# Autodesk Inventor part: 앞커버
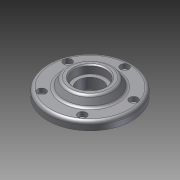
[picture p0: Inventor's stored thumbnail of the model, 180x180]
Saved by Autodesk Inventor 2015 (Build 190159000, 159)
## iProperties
Company: 한국ATC센터
Created: 2014-03
Part Number: 앞커버
Document SubType Name: Modeling
Designer: KYOUNG IL JANG
Density: 1 g/cm^3
Material: 일반
Appearance: Default
Author: KYOUNG IL JANG
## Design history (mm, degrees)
sketch "스케치1"
  geometry: C1 r 26 at (0, 0); C2 r 40 at (0, 0); 1 further point
  constraints: 2 centre point, 2 coincident
  dimensions: "d0" = 52 diameter of C1; "d1" = 80 diameter of C2
extrude "돌출1" new body sketch "스케치1" distance "d2" = 8; taper "d3" = 0 deg
extrude "돌출2" join sketch "스케치1" distance "d4" = 5; taper "d5" = 0 deg
sketch "스케치2"
  geometry: C1 r 25 at (0, 0); 1 further point
  constraints: 1 centre point, 1 coincident
  dimensions: "d6" = 50 diameter of C1
extrude "돌출3" join sketch "스케치2" distance "d7" = 8; taper "d8" = -30 deg
sketch "스케치3"
  geometry: C1 r 1.729 at (0, 33) reference; 1 further point
hole "구멍1" sketch "스케치3" at (0, 33) diameter "d9" = 4.5; stored, may be unused: countersink angle "d13" = 90 deg, drill point angle "d15" = 118 deg; dims "d10" = 6, "d11" = 8, "d12" = 4.4, "d14" = 8
hole "구멍2" diameter "d21" = 23; stored, may be unused: countersink angle "d25" = 90 deg, drill point angle "d27" = 118 deg; dims "d19" = 10, "d20" = 10, "d22" = 6, "d23" = 30, "d24" = 8, "d26" = 8
fillet "모깎기1" dims "d28" = 3, "d29" = 0.3
hole "구멍3" diameter "d32" = 40; stored, may be unused: countersink angle "d36" = 90 deg, drill point angle "d38" = 0 deg; dims "d30" = 10, "d31" = 10, "d33" = 6, "d34" = 30, "d35" = 8, "d37" = 3
fillet "모깎기2" dims "d39" = 3
chamfer "모따기1" distance "d40" = 1; stored, may be unused: second distance "d41" = 2, angle "d42" = 45 deg
node "솔리드1"
pattern_circular "원형 패턴1" dims angle "d17" = 360 deg
node "참조1"
